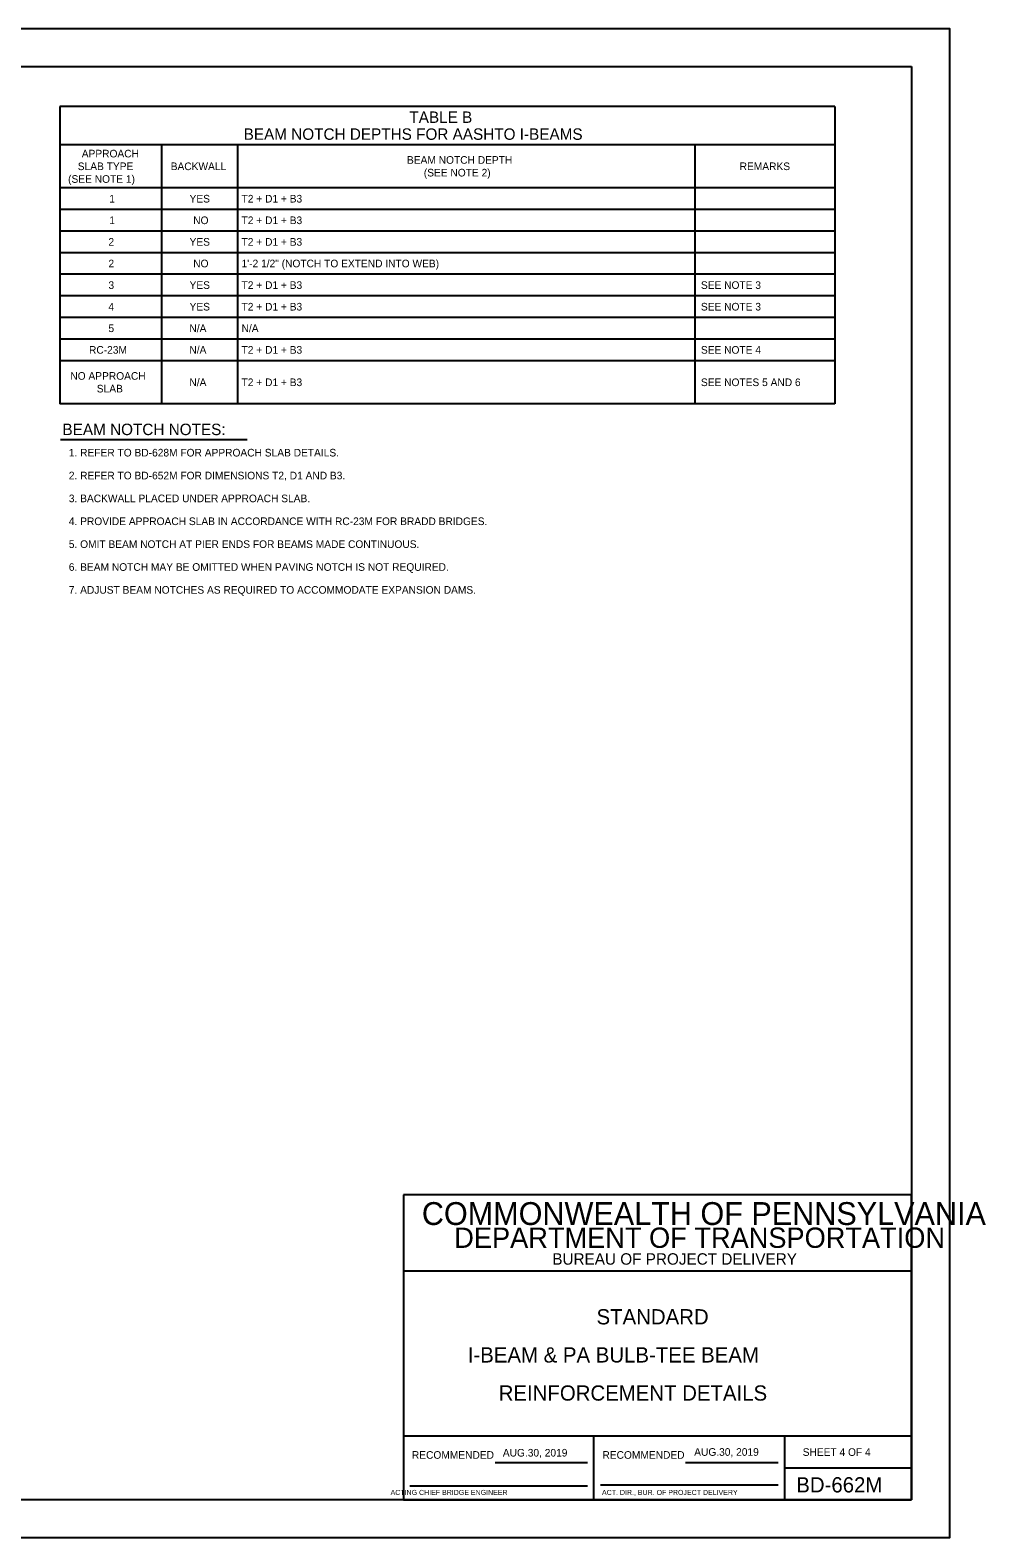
# Model space of a CAD drawing. Extents: x 637933 to 640019, y 298854 to 300042.
# Drawn here: x 639304 to 639680, y 298854 to 299447 of the extents above; entities that cross this region are included whole.
import ezdxf

# ---------------------------------------------------------------- set-up
doc = ezdxf.new("R2010")
doc.units = 0
doc.layers.add('1', color=7, linetype='Continuous')
doc.layers.add('PLT-BNDY', color=7, linetype='Continuous')

msp = doc.modelspace()

# ---------------------------------------------------------------- linework, layer by layer
at = {"layer": '1'}
for p, q in [((638864.93, 299433.12), (639650.94, 299433.12)), ((639650.94, 299433.12), (639650.94, 298869.12)), ((639620.69, 299417.39), (639315.69, 299417.39)), ((639315.69, 299417.39), (639315.69, 299300.39)), ((639620.69, 299417.39), (639620.69, 299300.39)), ((639620.69, 299402.39), (639315.69, 299402.39)), ((639355.69, 299402.39), (639355.69, 299300.39)), ((639385.69, 299402.39), (639385.69, 299300.39)), ((639565.69, 299402.39), (639565.69, 299300.39)), ((639620.69, 299385.39), (639315.69, 299385.39)), ((639620.69, 299376.89), (639315.69, 299376.89)), ((639620.69, 299368.39), (639315.69, 299368.39)), ((639620.69, 299359.89), (639315.69, 299359.89)), ((639620.69, 299351.39), (639315.69, 299351.39)), ((639620.69, 299342.89), (639315.69, 299342.89)), ((639620.69, 299334.39), (639315.69, 299334.39)), ((639620.69, 299325.89), (639315.69, 299325.89)), ((639620.69, 299317.39), (639315.69, 299317.39)), ((639620.69, 299300.39), (639315.69, 299300.39)), ((639316.02, 299286.37), (639389.44, 299286.37)), ((639650.94, 298989.12), (639450.94, 298989.12)), ((639450.94, 298989.12), (639450.94, 298869.12)), ((639650.94, 298869.12), (639650.94, 298989.12)), ((639650.94, 298959.12), (639450.94, 298959.12)), ((639650.94, 298894.12), (639450.94, 298894.12)), ((639525.94, 298869.12), (639525.94, 298894.12)), ((639600.94, 298894.12), (639600.94, 298869.12)), ((639487.02, 298883.83), (639523.44, 298883.83)), ((639562.02, 298883.83), (639598.44, 298883.83)), ((639600.94, 298881.62), (639650.94, 298881.62)), ((639453.44, 298874.62), (639523.44, 298874.62)), ((639528.44, 298874.99), (639598.44, 298874.99)), ((639650.94, 298869.12), (638864.93, 298869.12)), ((639450.94, 298869.12), (639650.94, 298869.12))]:
    msp.add_line(p, q, dxfattribs=at)
at = {"layer": 'PLT-BNDY'}
msp.add_lwpolyline([(638824.93, 299448.12), (639665.93, 299448.12), (639665.93, 298854.12), (638824.93, 298854.12)], close=True, dxfattribs=at)

# ---------------------------------------------------------------- texts
at = {"layer": '1'}
for s, height, p in [('TABLE B', 4.5, (639453.29, 299410.97)), ('BEAM NOTCH DEPTHS FOR AASHTO I-BEAMS', 4.5, (639388.06, 299404.31)), ('T2 + D1 + B3', 3, (639387.23, 299379.64)), ('T2 + D1 + B3', 3, (639387.23, 299371.14)), ('T2 + D1 + B3', 3, (639387.23, 299362.64)), ('1\'-2 1/2" (NOTCH TO EXTEND INTO WEB)', 3, (639387.23, 299354.14)), ('T2 + D1 + B3', 3, (639387.23, 299345.64)), ('SEE NOTE 3', 3, (639568.03, 299345.64)), ('T2 + D1 + B3', 3, (639387.23, 299337.14)), ('SEE NOTE 3', 3, (639568.03, 299337.14)), ('N/A', 3, (639387.23, 299328.64)), ('T2 + D1 + B3', 3, (639387.23, 299320.14)), ('SEE NOTE 4', 3, (639568.03, 299320.14)), ('T2 + D1 + B3', 3, (639387.23, 299307.39)), ('SEE NOTES 5 AND 6', 3, (639568.03, 299307.39)), ('BEAM NOTCH NOTES:', 4.5, (639316.75, 299288.1)), (' 1. REFER TO BD-628M FOR APPROACH SLAB DETAILS.', 3, (639318.13, 299279.69)), (' 2. REFER TO BD-652M FOR DIMENSIONS T2, D1 AND B3.', 3, (639318.13, 299270.69)), (' 3. BACKWALL PLACED UNDER APPROACH SLAB.', 3, (639318.13, 299261.69)), (' 4. PROVIDE APPROACH SLAB IN ACCORDANCE WITH RC-23M FOR BRADD BRIDGES.', 3, (639318.13, 299252.69)), (' 5. OMIT BEAM NOTCH AT PIER ENDS FOR BEAMS MADE CONTINUOUS.', 3, (639318.13, 299243.69)), (' 6. BEAM NOTCH MAY BE OMITTED WHEN PAVING NOTCH IS NOT REQUIRED.', 3, (639318.13, 299234.69)), (' 7. ADJUST BEAM NOTCHES AS REQUIRED TO ACCOMMODATE EXPANSION DAMS.', 3, (639318.13, 299225.69)), ('COMMONWEALTH OF PENNSYLVANIA', 9, (639458.19, 298977.24)), ('DEPARTMENT OF TRANSPORTATION', 8.0003, (639470.94, 298968.24)), ('BUREAU OF PROJECT DELIVERY', 4.5, (639509.53, 298961.62)), ('STANDARD', 6, (639526.94, 298938.12)), ('I-BEAM & PA BULB-TEE BEAM', 6, (639476.26, 298923.12)), ('REINFORCEMENT DETAILS', 6, (639488.44, 298908.12)), ('AUG.30, 2019', 3, (639490.06, 298886.11)), ('AUG.30, 2019', 3, (639565.38, 298886.41)), ('SHEET 4 OF 4', 3, (639608.09, 298886.37)), ('RECOMMENDED', 3, (639454.27, 298885.24)), ('RECOMMENDED', 3, (639529.27, 298885.24)), ('BD-662M', 6, (639605.56, 298871.99)), ('       ACTING CHIEF BRIDGE ENGINEER', 2.0002, (639440.52, 298870.99)), ('ACT. DIR., BUR. OF PROJECT DELIVERY', 2.0002, (639529.09, 298870.99))]:
    msp.add_text(s, height=height, dxfattribs=at).set_placement(p)
for s, p in [('APPROACH', (639324.34, 299397.39)), ('SLAB TYPE', (639322.77, 299392.39)), ('BACKWALL', (639359.34, 299392.39)), ('BEAM NOTCH DEPTH', (639452.34, 299394.89)), ('REMARKS', (639583.27, 299392.39)), ('(SEE NOTE 1)', (639318.96, 299387.39)), ('(SEE NOTE 2)', (639458.96, 299389.89)), ('1', (639335.18, 299379.64)), ('YES', (639366.77, 299379.64)), ('1', (639335.18, 299371.14)), ('NO', (639368.21, 299371.14)), ('2', (639334.84, 299362.64)), ('YES', (639366.77, 299362.64)), ('2', (639334.84, 299354.14)), ('NO', (639368.21, 299354.14)), ('3', (639334.84, 299345.64)), ('YES', (639366.77, 299345.64)), ('4', (639334.84, 299337.14)), ('YES', (639366.77, 299337.14)), ('5', (639334.84, 299328.64)), ('N/A', (639366.71, 299328.64)), ('RC-23M', (639327.19, 299320.14)), ('N/A', (639366.71, 299320.14)), ('NO APPROACH', (639319.84, 299309.89)), ('N/A', (639366.71, 299307.39)), ('SLAB', (639330.26, 299304.89))]:
    msp.add_text(s, height=3, rotation=360, dxfattribs=at).set_placement(p)

doc.saveas('drawing.dxf')
